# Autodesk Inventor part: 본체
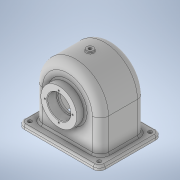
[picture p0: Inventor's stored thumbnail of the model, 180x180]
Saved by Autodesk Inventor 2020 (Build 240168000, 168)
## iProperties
Created: 2022-09
Part Number: 본체
Material: 일반
Document SubType Name: Modeling
Designer: Administrator
Density: 1 g/cm^3
Appearance: 기본값
Author: Administrator
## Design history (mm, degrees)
sketch "스케치1"
  geometry: L1 (-54, 70)-(54, 70); L2 (54, 70)-(54, -70); L3 (54, -70)-(-54, -70); L4 (-54, -70)-(-54, 70); L5 (-54, 70)-(54, -70); L6 (54, 70)-(-54, -70); 1 further point
  constraints: 12 end point, 2 midpoint, 2 parallel, 1 horizontal, 1 perpendicular
  dimensions: "d0" = 140 distance between parallel lines of L3 L1; "d1" = 108 distance between parallel lines of L2 L4
extrude "돌출1" new body sketch "스케치1" distance "d2" = 7; taper "d3" = 0 deg
node "작업 평면3"
sketch "스케치10"
  geometry: L1 (64, 127)-(7, 127); L2 (7, 0)-(7, 140) reference; L3 (64, 13)-(7, 13); L4 (0, 0)-(0, 140) reference; A1 r 57 centre (64, 70) between (64, 13) and (64, 127); 1 further point
  constraints: 4 end point, 2 point on circle, 2 point on line, 2 tangent, 1 centre point, 1 horizontal, 1 horizontal alignment, 1 perpendicular
  dimensions: "d42" = 57 radius of A1; "d43" = 64 distance from line of A1.centre L4
extrude "돌출7" join sketch "스케치10" distance "d44" = 78; taper "d45" = 0 deg
fillet "모깎기4" dims "d46" = 14
node "작업 평면4"
sketch "스케치11"
  geometry: L1 (0, 140)-(0, 0) reference; C1 r 31 at (64, 70); 2 further points
  constraints: 1 centre point, 1 horizontal alignment, 1 midpoint
  dimensions: "d48" = 31 radius of C1; "d49" = 64 distance from line of C1.centre L1
feature "쉘3" dims "d50" = 5
extrude "돌출8" join sketch "스케치11" stored distance "d51" = 78; taper "d52" = 0 deg
sketch "스케치13"
  geometry: L1 (-39, 64)-(-39, 107) reference; L2 (-39, 64)-(71.768, 64); L3 (54, 33)-(54, 95) reference; L4 (54, 84)-(38, 84); L5 (38, 84)-(38, 81.5); L6 (38, 81.5)-(33, 81.5); L7 (39, 107)-(39, 64) reference; L8 (33, 81.5)-(33, 64); L9 (25, 64)-(39, 64) reference; 3 further points
  constraints: 10 end point, 3 perpendicular, 2 horizontal, 2 point on line
  dimensions: "d53" = 40 diameter of L4 L2; "d54" = 35 diameter of L6 L2; "d55" = 16 distance from line of L4.end L3; "d56" = 5 distance from line of L5.end L8
revolve "회전3" sketch "스케치13" stored, may be unused: angle "d57" = 90 deg
sketch "스케치15"
  geometry: C1 r 32 at (-64, 70); A1 r 43 centre (-64, 70) between (-64, 113) and (-64, 27) reference; 1 further point
  constraints: 1 centre point, 1 coincident
  dimensions: "d64" = 32 radius of C1
extrude "돌출10" cut sketch "스케치15" distance "d65" = 5; taper "d66" = 0 deg
node "작업 평면6"
sketch "스케치17"
  geometry: C1 r 28 at (0, 0); 1 further point
  constraints: 1 centre point
  dimensions: "d72" = 28 radius of C1
extrude "돌출12" join sketch "스케치17" stored distance "d73" = 14; taper "d74" = 30 deg
sketch "스케치18"
  geometry: C1 r 20 at (0, 0) reference; C2 r 20 at (0, 0); 1 further point
  constraints: 1 centre point, 1 coincident
  dimensions: "d75" = 20 radius of C2
extrude "돌출13" cut sketch "스케치18" distance "d76" = 16; taper "d77" = 0 deg
sketch "스케치19" dims "d78" = 24
  geometry: C1 r 20 at (0, 0) reference; C2 r 28 at (0, 0) reference; 3 further points
  constraints: 2 horizontal alignment, 1 coincident, 2 other
hole "구멍1" sketch "스케치19" at (24, 0) diameter "d79" = 2.459; stored, may be unused: countersink angle "d83" = 90 deg, drill point angle "d85" = 118 deg; dims "d80" = 7, "d81" = 8, "d82" = 4.4, "d84" = 9
sketch "스케치20" dims "d89" = 24
  geometry: C1 r 20 at (0, 0) reference; C2 r 32 at (0, 0) reference; 3 further points
  constraints: 2 horizontal alignment, 1 coincident, 2 other
hole "구멍2" sketch "스케치20" at (-24, 0) diameter "d90" = 2.459; stored, may be unused: countersink angle "d94" = 90 deg, drill point angle "d96" = 118 deg; dims "d91" = 7, "d92" = 8, "d93" = 4.4, "d95" = 9
node "작업 평면7"
sketch "스케치21"
  geometry: C1 r 6 at (49, 65); 1 further point
  constraints: 1 centre point, 1 coincident
  dimensions: "d101" = 6 radius of C1
extrude "돌출14" join sketch "스케치21" stored distance "d102" = 16; taper "d103" = 0 deg
fillet "모깎기5" dims "d104" = 1
sketch "스케치22"
  geometry: C1 r 6 at (0, 0) reference; 2 further points
  constraints: 1 coincident
hole "구멍3" sketch "스케치22" at (0, 0) diameter "d105" = 5.1881; stored, may be unused: countersink angle "d109" = 90 deg, drill point angle "d111" = 118 deg; dims "d106" = 12, "d107" = 8, "d108" = 4.4, "d110" = 15
chamfer "모따기1" distance "d112" = 1; stored, may be unused: second distance "d113" = 2, angle "d114" = 45 deg
chamfer "모따기2" distance "d115" = 1; stored, may be unused: second distance "d116" = 2, angle "d117" = 45 deg
fillet "모깎기6" dims "d118" = 10, "d119" = 3
sketch "스케치23"
  geometry: L1 (64, 0)-(64, 54) reference; L2 (69, 64)-(-19, 64) reference; 2 further points
  constraints: 1 other
  dimensions: "d120" = 39 distance from line of point (25, 47) L1; "d121" = 17 distance from line of point (25, 47) L2
feature "엠보싱1" sketch "스케치23" dims "d0" = 140, "d1" = 108, "d122" = 0.5, "d123" = 0
fillet "모깎기7" dims "d124" = 3
fillet "모깎기8" dims "d125" = 3
sketch "스케치26"
  geometry: L1 (49, 65)-(49, -65) reference; L2 (49, -65)-(-49, -65) reference; L3 (-49, -65)-(-49, 65) reference; L4 (-49, 65)-(49, 65) reference; L5 (-49, 65)-(49, 65) reference; L6 (49, -65)-(-49, -65); L7 (-49, -65)-(-49, 65); L8 (-49, 65)-(49, 65); L9 (49, 65)-(49, -65); L10 (49, -65)-(-49, 65); L11 (-49, -65)-(49, 65); L12 (25, 52)-(-25, 52); L13 (-34, 43)-(-34, -43); L14 (-25, -52)-(25, -52); L15 (34, -43)-(34, 43); L16 (34, 52)-(-34, -52); L17 (-34, 52)-(34, -52); L18 (-34, 43)-(-34, -43) reference; L19 (34, -43)-(34, 43) reference; L20 (25, 52)-(-25, 52) reference; L21 (-25, -52)-(25, -52) reference; C1 r 2.594 at (0, 0) reference; A1 r 9 centre (-25, 43) between (-25, 52) and (-34, 43); A2 r 9 centre (25, 43) between (34, 43) and (25, 52); A3 r 9 centre (25, -43) between (25, -52) and (34, -43); A4 r 9 centre (-25, -43) between (-34, -43) and (-25, -52); 1 further point
  constraints: 24 end point, 9 point on line, 8 point on circle, 8 tangent, 4 centre point, 4 midpoint, 4 parallel, 2 horizontal, 2 perpendicular, 1 equal radius
  dimensions: "d135" = 9 radius of A1; "d136" = 9 radius of A2; "d137" = 9 radius of A4 (derived); "d138" = 104 distance between parallel lines of L12 L21
extrude "돌출16" join sketch "스케치26" distance "d139" = 2; taper "d140" = 0 deg
sketch "스케치24"
  geometry: A1 r 7 centre (44, 60) between (51, 60) and (44, 67) reference; A2 r 7 centre (-44, 60) between (-44, 67) and (-51, 60) reference; A3 r 7 centre (-44, -60) between (-51, -60) and (-44, -67) reference; A4 r 7 centre (44, -60) between (44, -67) and (51, -60) reference; 5 further points
  constraints: 4 coincident
hole "구멍4" sketch "스케치24" at (-44, 60), (44, -60), (-44, -60), (44, 60) diameter "d126" = 6.6; stored, may be unused: countersink angle "d130" = 90 deg, drill point angle "d132" = 0 deg; dims "d127" = 12, "d128" = 8, "d129" = 4.4, "d131" = 16
node "솔리드1"
pattern_circular "원형 패턴1" dims angle "d87" = 360 deg
pattern_circular "원형 패턴2" dims angle "d98" = 360 deg
feature "A9D066F2-1C7D-4E18-AEED-F7BC21143FA4" dims "d126" = 6.6, "d127" = 12, "d128" = 8, "d129" = 4.4, "d130" = 90 deg, "d131" = 16, "d132" = 0
other parameters: "d40" = -15, "d47" = 15, "d71" = 16, "d100" = -122
